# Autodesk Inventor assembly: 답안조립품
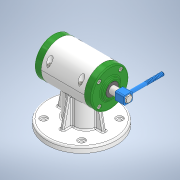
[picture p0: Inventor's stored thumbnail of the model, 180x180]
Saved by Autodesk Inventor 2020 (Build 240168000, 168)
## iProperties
Created: 2023-11
Part Number: 답안조립품
Document SubType Name: Assembly
Designer: oem
Mass: 1423.06 g
Surface Area: 1331.57 cm^2
Volume: 399.661 cm^3
Density: 3.56067 g/cm^3
Author: oem
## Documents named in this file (14)
- C:\Users\oem\Desktop\631106V1007\답안조립품.iam
- C:\Users\oem\Desktop\631106V1007\본체.ipt
- C:\Users\oem\Desktop\631106V1007\본체상부커버.ipt
- C:\Users\oem\Desktop\631106V1007\앞커버.ipt
- C:\Users\oem\Desktop\631106V1007\뒤커버.ipt
- C:\Users\oem\Desktop\631106V1007\베어링 6202.ipt
- C:\Users\oem\Desktop\631106V1007\오일실 12 22 7.ipt
- C:\Users\oem\Desktop\631106V1007\편심축.ipt
- C:\Users\oem\Desktop\631106V1007\부시.ipt
- C:\Users\oem\Desktop\631106V1007\슬라이드.ipt
- C:\Users\oem\Desktop\631106V1007\가변스프링.ipt
- C:\Users\oem\Desktop\631106V1007\볼트 M3x8.ipt
- C:\Users\oem\Desktop\631106V1007\볼트 M4x12.ipt
- C:\Users\oem\Desktop\631106V1007\레버.ipt
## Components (1 placed, 1 different names)
1. 가변스프링:1
